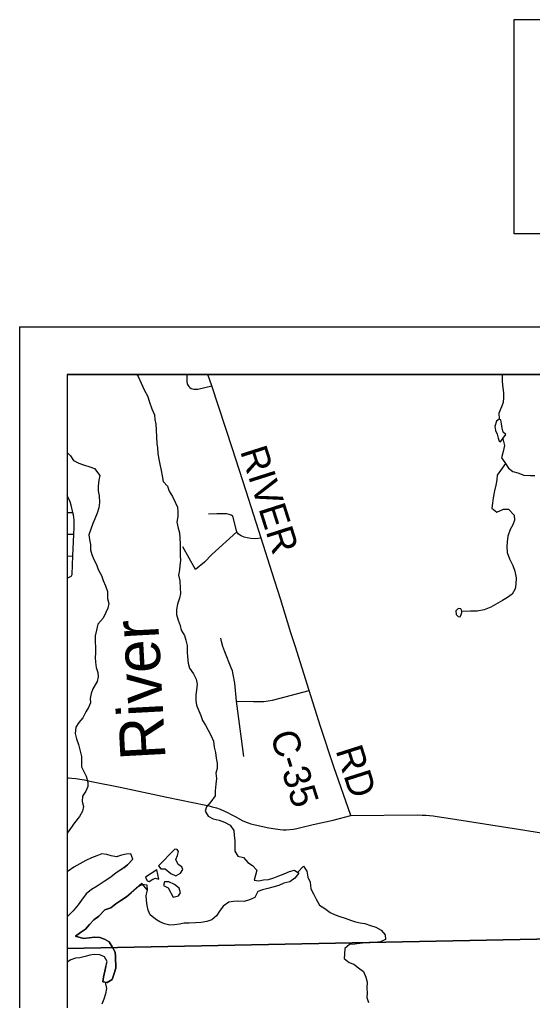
# Model space of a CAD drawing. Extents: x 0 to 34, y 0 to 22.
# Drawn here: x 3.344 to 4.422, y 18.608 to 20.67 of the extents above; entities that cross this region are included whole.
import ezdxf

# ---------------------------------------------------------------- set-up
doc = ezdxf.new("R2010")
doc.units = 0
for name, color, linetype in [('GM_X_Corporation', 7, 'Continuous'), ('GM_X_County_Road', 7, 'Continuous'), ('GM_X_County_Road_Text', 7, 'Continuous'), ('GM_X_Major_Lake', 7, 'Continuous'), ('GM_X_Major_River_Text', 7, 'Continuous'), ('GM_X_Minor_Lake', 7, 'Continuous'), ('GM_X_Minor_River', 7, 'Continuous'), ('GM_X_Township_Road', 7, 'Continuous'), ('SH_Data', 7, 'Continuous'), ('SH_Text', 7, 'Continuous')]:
    doc.layers.add(name, color=color, linetype=linetype)

msp = doc.modelspace()

# ---------------------------------------------------------------- linework, layer by layer
at = {"layer": 'GM_X_Corporation'}
msp.add_lwpolyline([(6.9951, 19.9239), (3.4438, 19.9239), (3.4438, 18.7173), (4.784, 18.7437), (5.4919, 18.7569), (5.8701, 18.7643), (7.0169, 18.7868), (7.0072, 19.2641), (7.0062, 19.3415), (7.0002, 19.6505)], close=True, dxfattribs=at)
msp.add_lwpolyline([(7.0169, 18.7868), (5.8701, 18.7643), (5.4919, 18.7569), (4.784, 18.7437), (3.4438, 18.7173), (3.4438, 13.5923), (3.5133, 13.5939), (4.9278, 13.619), (5.5741, 13.6306), (5.8662, 13.6357), (7.1049, 13.6572)], dxfattribs=at)
at = {"layer": 'GM_X_County_Road'}
for points in [[(4.0404, 18.9967), (4.0048, 19.099), (3.9766, 19.1839), (3.9528, 19.2594), (3.9233, 19.3534), (3.9144, 19.381), (3.9075, 19.4042), (3.8922, 19.4522), (3.8753, 19.5071), (3.8519, 19.5801), (3.8203, 19.6783), (3.7912, 19.7674), (3.748, 19.8997), (3.74, 19.9239)], [(3.4438, 19.0761), (3.4464, 19.076), (3.4536, 19.0756), (3.4619, 19.0746), (3.4703, 19.0735), (3.4804, 19.0716), (3.4953, 19.0685), (3.5551, 19.0562), (3.6537, 19.0356)], [(3.6537, 19.0356), (3.7356, 19.0186), (3.7426, 19.0169), (3.7491, 19.0151), (3.7576, 19.0126), (3.7655, 19.01), (3.7733, 19.0069), (3.7813, 19.0032), (3.7888, 18.9992), (3.7956, 18.9956), (3.7974, 18.9946)], [(3.7974, 18.9946), (3.8135, 18.9859), (3.8224, 18.9819), (3.8299, 18.9796), (3.8365, 18.9776), (3.8457, 18.9756), (3.8683, 18.9709), (3.8821, 18.9685), (3.8916, 18.9671), (3.8982, 18.9667), (3.9045, 18.9668), (3.9119, 18.9671), (3.9198, 18.9681), (3.9267, 18.9693), (3.9328, 18.9709), (3.9613, 18.9778), (4.003, 18.9873), (4.0404, 18.9967)], [(4.0404, 18.9967), (4.1797, 18.9979), (4.1902, 18.9977), (4.1981, 18.9975), (4.2061, 18.9971), (4.2133, 18.9962), (4.2223, 18.9949), (4.25, 18.9904), (4.4062, 18.9661), (4.6004, 18.9348), (4.7799, 18.9077)]]:
    msp.add_lwpolyline(points, dxfattribs=at)
at = {"layer": 'GM_X_Major_Lake'}
for points in [[(3.5906, 19.9239), (3.593, 19.9197), (3.5996, 19.9057), (3.6062, 19.8905), (3.6128, 19.8788), (3.6171, 19.8659), (3.6217, 19.8515), (3.6272, 19.839), (3.628, 19.8295), (3.63, 19.8193), (3.6313, 19.8075), (3.6318, 19.7919), (3.6327, 19.779), (3.6335, 19.7695), (3.6348, 19.7577), (3.6368, 19.7456), (3.6388, 19.735), (3.6415, 19.7221), (3.6439, 19.7107), (3.6459, 19.6989), (3.6548, 19.6891), (3.6583, 19.6785), (3.6652, 19.6671), (3.671, 19.6558), (3.6761, 19.6448), (3.6765, 19.6353), (3.6766, 19.625), (3.6748, 19.6136), (3.6776, 19.6007), (3.68, 19.5909), (3.6808, 19.5802), (3.6817, 19.5669), (3.6814, 19.5555), (3.6812, 19.5434), (3.6824, 19.5331), (3.681, 19.5224), (3.6803, 19.5129), (3.6777, 19.5023), (3.6805, 19.4901), (3.6814, 19.4749), (3.6819, 19.4635), (3.6804, 19.454), (3.6756, 19.4414), (3.6738, 19.4296), (3.6739, 19.419), (3.677, 19.4072), (3.6813, 19.3963), (3.6837, 19.3864), (3.6903, 19.3754), (3.6934, 19.3656), (3.6962, 19.3542), (3.6959, 19.3405), (3.6968, 19.3302), (3.6984, 19.3173), (3.7012, 19.3067), (3.7092, 19.2946), (3.7154, 19.2833), (3.7174, 19.2726), (3.716, 19.2605), (3.7146, 19.2506), (3.7143, 19.2384), (3.7159, 19.2289), (3.721, 19.2168), (3.7249, 19.2069), (3.7284, 19.1967), (3.7349, 19.1869), (3.7404, 19.1759), (3.7469, 19.1646), (3.7516, 19.1532), (3.7528, 19.1407), (3.7556, 19.1293), (3.7572, 19.1175), (3.7592, 19.1065), (3.7593, 19.0955)], [(3.4438, 19.7601), (3.4507, 19.7528), (3.4569, 19.743), (3.4687, 19.7374), (3.4783, 19.7337), (3.4912, 19.73), (3.5015, 19.7263), (3.5123, 19.7115), (3.5105, 19.7016), (3.5091, 19.6894), (3.5092, 19.6796), (3.5112, 19.6686), (3.512, 19.6549), (3.5102, 19.6438), (3.5069, 19.6324), (3.5017, 19.6202), (3.498, 19.6103), (3.4935, 19.5985), (3.4895, 19.5867), (3.4911, 19.5768), (3.4927, 19.5662), (3.4928, 19.5551), (3.4959, 19.5457), (3.5002, 19.5351), (3.5052, 19.5244), (3.5091, 19.5138), (3.5161, 19.501), (3.5196, 19.4907), (3.5246, 19.4798), (3.5289, 19.468), (3.5287, 19.4528), (3.5314, 19.4426), (3.5296, 19.433), (3.5251, 19.4235), (3.5195, 19.4117), (3.5086, 19.3987), (3.5057, 19.3865), (3.5028, 19.3747), (3.5031, 19.3382), (3.5024, 19.3287), (3.5036, 19.3192), (3.5045, 19.3078), (3.508, 19.2976), (3.5092, 19.2881), (3.507, 19.2782), (3.4981, 19.2629), (3.4943, 19.2534), (3.4925, 19.2431), (3.4926, 19.2336), (3.4889, 19.224), (3.4833, 19.2145), (3.4769, 19.2023), (3.4683, 19.1923), (3.4623, 19.1824), (3.4609, 19.1695), (3.4632, 19.1581), (3.4675, 19.146), (3.4707, 19.135), (3.4738, 19.1209), (3.4743, 19.1103), (3.474, 19.0993), (3.4791, 19.0894), (3.4837, 19.0792), (3.4873, 19.0671), (3.4873, 19.0576), (3.4832, 19.048), (3.4761, 19.0373), (3.4755, 19.0263), (3.4782, 19.0161), (3.4764, 19.0062), (3.4697, 18.9947), (3.4595, 18.9817)], [(3.7593, 19.0955), (3.7564, 19.086), (3.7576, 19.0746), (3.7566, 19.0624), (3.7552, 19.0487), (3.7553, 19.0384), (3.7463, 19.0254), (3.7369, 19.0151), (3.7339, 19.0056), (3.7401, 18.9957), (3.7512, 18.9901), (3.7637, 18.9868), (3.7744, 18.9827), (3.7863, 18.9764), (3.7947, 18.965), (3.7952, 18.9551), (3.7964, 18.9441), (3.7967, 18.9217), (3.8028, 18.9115), (3.815, 18.9082), (3.8235, 18.898), (3.8338, 18.892), (3.843, 18.8818), (3.8397, 18.8711), (3.8371, 18.8608), (3.847, 18.8598), (3.8569, 18.8618), (3.8672, 18.8622), (3.8785, 18.8657), (3.8892, 18.87), (3.9005, 18.8743), (3.9115, 18.8789), (3.9218, 18.882), (3.9313, 18.8753), (3.9223, 18.8649), (3.9121, 18.8576), (3.8992, 18.8549), (3.889, 18.8499), (3.8764, 18.8463), (3.8662, 18.8436), (3.8548, 18.8408), (3.8446, 18.8373), (3.8382, 18.8247), (3.8272, 18.8193), (3.8159, 18.8158), (3.8029, 18.8165), (3.7934, 18.8164), (3.7835, 18.8144), (3.7722, 18.806), (3.7639, 18.7956), (3.7579, 18.7857), (3.7481, 18.7773), (3.7379, 18.7741), (3.7254, 18.7718), (3.7136, 18.7709), (3.7006, 18.7704), (3.6896, 18.7703), (3.6801, 18.7687), (3.6695, 18.7667), (3.6596, 18.7663), (3.6485, 18.7692), (3.639, 18.773), (3.6294, 18.779), (3.6187, 18.788), (3.6144, 18.7978), (3.6121, 18.8077), (3.6105, 18.818), (3.61, 18.829), (3.6125, 18.84), (3.6121, 18.8503), (3.6018, 18.8521), (3.5897, 18.8448)], [(3.7593, 19.0955), (3.7564, 19.086), (3.7576, 19.0746), (3.7566, 19.0624), (3.7552, 19.0487), (3.7553, 19.0384), (3.7463, 19.0254), (3.7369, 19.0151), (3.7339, 19.0056), (3.7401, 18.9957), (3.7512, 18.9901), (3.7637, 18.9868), (3.7744, 18.9827), (3.7863, 18.9764), (3.7947, 18.965), (3.7952, 18.9551), (3.7964, 18.9441), (3.7967, 18.9217), (3.8028, 18.9115), (3.815, 18.9082), (3.8235, 18.898), (3.8338, 18.892), (3.843, 18.8818), (3.8397, 18.8711), (3.8371, 18.8608), (3.847, 18.8598), (3.8569, 18.8618), (3.8672, 18.8622), (3.8785, 18.8657), (3.8892, 18.87), (3.9005, 18.8743), (3.9115, 18.8789), (3.9218, 18.882), (3.9313, 18.8753), (3.9223, 18.8649), (3.9121, 18.8576), (3.8992, 18.8549), (3.889, 18.8499), (3.8764, 18.8463), (3.8662, 18.8436), (3.8548, 18.8408), (3.8446, 18.8373), (3.8382, 18.8247), (3.8272, 18.8193), (3.8159, 18.8158), (3.8029, 18.8165), (3.7934, 18.8164), (3.7835, 18.8144), (3.7722, 18.806), (3.7639, 18.7956), (3.7579, 18.7857), (3.7481, 18.7773), (3.7379, 18.7741), (3.7254, 18.7718), (3.7136, 18.7709), (3.7006, 18.7704), (3.6896, 18.7703), (3.6801, 18.7687), (3.6695, 18.7667), (3.6596, 18.7663), (3.6485, 18.7692), (3.639, 18.773), (3.6294, 18.779), (3.6187, 18.788), (3.6144, 18.7978), (3.6121, 18.8077), (3.6105, 18.818), (3.61, 18.829), (3.6125, 18.84), (3.6008, 18.8536)], [(3.4595, 18.9817), (3.4505, 18.9695), (3.4438, 18.9598)], [(3.6359, 18.8909), (3.641, 18.8849), (3.6501, 18.885), (3.662, 18.8752), (3.6723, 18.87), (3.6825, 18.8759), (3.687, 18.8831), (3.685, 18.8892), (3.6773, 18.8937), (3.6726, 18.9043), (3.6756, 18.913), (3.6781, 18.9211), (3.675, 18.9256), (3.6704, 18.9263)], [(3.6704, 18.9263), (3.6359, 18.8909)], [(3.5631, 18.887), (3.5706, 18.8933), (3.5819, 18.9048), (3.5776, 18.9165), (3.5677, 18.9157), (3.5582, 18.9137), (3.5476, 18.9102), (3.5366, 18.9124), (3.527, 18.915), (3.5168, 18.916), (3.5062, 18.9121), (3.4948, 18.9079), (3.483, 18.9024), (3.4702, 18.8951), (3.4577, 18.8882), (3.446, 18.8797), (3.4438, 18.8786)], [(3.5819, 18.9048), (3.5706, 18.8933), (3.56, 18.8844), (3.5468, 18.876), (3.5355, 18.8671), (3.5218, 18.8583), (3.5067, 18.8483), (3.495, 18.841), (3.4837, 18.8325), (3.4739, 18.8188), (3.4668, 18.8092), (3.4566, 18.7962), (3.4453, 18.7851), (3.4438, 18.784)], [(3.5631, 18.887), (3.5468, 18.876), (3.5355, 18.8671), (3.5218, 18.8583), (3.5067, 18.8483), (3.495, 18.841), (3.4837, 18.8325), (3.4739, 18.8188), (3.4668, 18.8092), (3.4566, 18.7962), (3.4453, 18.7851), (3.4438, 18.784)], [(3.6089, 18.8674), (3.612, 18.8598), (3.6166, 18.8583), (3.6241, 18.863), (3.6298, 18.865), (3.6363, 18.8631), (3.6326, 18.8825)], [(3.6326, 18.8825), (3.6089, 18.8674)], [(3.6008, 18.8536), (3.5787, 18.834), (3.5689, 18.8256), (3.5564, 18.8179), (3.5459, 18.811), (3.5357, 18.8025), (3.5231, 18.7982), (3.5107, 18.7852), (3.5001, 18.7775), (3.4911, 18.7676), (3.4821, 18.758), (3.4722, 18.7511), (3.4613, 18.743), (3.4784, 18.7382), (3.4902, 18.7398), (3.5012, 18.7411), (3.5123, 18.7404), (3.5222, 18.7367), (3.5321, 18.731), (3.5383, 18.7208), (3.5449, 18.7099), (3.5457, 18.7004), (3.5459, 18.6757), (3.5422, 18.6623), (3.5382, 18.6524), (3.5283, 18.6455), (3.5188, 18.6473), (3.5199, 18.6572), (3.5228, 18.6694), (3.5254, 18.6793)], [(3.5254, 18.6793), (3.5228, 18.6694), (3.5199, 18.6572), (3.5188, 18.6473), (3.5283, 18.6455), (3.5382, 18.6524), (3.5422, 18.6623), (3.5459, 18.6757), (3.5457, 18.7004), (3.5449, 18.7099), (3.5383, 18.7208), (3.5321, 18.731), (3.5222, 18.7367), (3.5123, 18.7404), (3.5012, 18.7411), (3.4902, 18.7398), (3.4784, 18.7382), (3.4613, 18.743), (3.4722, 18.7511), (3.4821, 18.758), (3.4911, 18.7676), (3.5001, 18.7775), (3.5107, 18.7852), (3.5231, 18.7982), (3.5357, 18.8025), (3.5459, 18.811), (3.5564, 18.8179), (3.5689, 18.8256), (3.5787, 18.834), (3.5897, 18.8448)], [(3.6665, 18.8255), (3.6779, 18.8283), (3.682, 18.8344), (3.6795, 18.8439), (3.6699, 18.8521), (3.6577, 18.8577), (3.6482, 18.8576), (3.6464, 18.8499), (3.6563, 18.8451)], [(3.6563, 18.8451), (3.6665, 18.8255)], [(3.5254, 18.6793), (3.5279, 18.6896), (3.5225, 18.6998), (3.5122, 18.7043), (3.5008, 18.7046), (3.4913, 18.703), (3.4814, 18.7002), (3.4708, 18.6979), (3.4613, 18.6966), (3.4518, 18.6931), (3.4438, 18.6886)]]:
    msp.add_lwpolyline(points, dxfattribs=at)
at = {"layer": 'GM_X_Minor_Lake'}
for points in [[(4.3667, 19.7977), (4.3605, 19.8029), (4.3587, 19.8112), (4.3574, 19.8203), (4.3561, 19.8282), (4.3526, 19.8301), (4.347, 19.8257), (4.3434, 19.8146), (4.3448, 19.8059), (4.348, 19.7984), (4.3501, 19.7897), (4.3522, 19.7837), (4.3552, 19.7822)], [(4.3552, 19.7822), (4.3667, 19.7977)], [(4.2714, 19.4313), (4.2672, 19.4319), (4.2646, 19.4307), (4.2609, 19.4272), (4.2618, 19.4193), (4.2661, 19.4152), (4.2703, 19.4145), (4.2721, 19.4191)], [(4.2721, 19.4191), (4.2737, 19.4236), (4.2741, 19.4259), (4.2735, 19.4283), (4.2714, 19.4313)]]:
    msp.add_lwpolyline(points, dxfattribs=at)
at = {"layer": 'GM_X_Minor_River'}
for points in [[(4.3588, 19.9239), (4.3585, 19.9203), (4.3587, 19.9093), (4.3598, 19.896), (4.3612, 19.8854), (4.3614, 19.8755), (4.3605, 19.8652), (4.3573, 19.8556), (4.3519, 19.8422), (4.3524, 19.8299)], [(4.3602, 19.7889), (4.3638, 19.7748), (4.361, 19.7618), (4.3572, 19.7488), (4.3642, 19.7391), (4.3717, 19.7271), (4.3814, 19.7201), (4.3918, 19.7169), (4.4044, 19.7119), (4.4177, 19.7118), (4.4276, 19.7117)], [(4.3658, 19.7366), (4.3485, 19.7121), (4.3476, 19.7026), (4.3452, 19.6915), (4.3428, 19.6793), (4.3394, 19.6648), (4.3381, 19.6533), (4.3372, 19.6427), (4.3473, 19.6345), (4.3616, 19.6409), (4.3723, 19.6404), (4.384, 19.6278), (4.3849, 19.6179), (4.381, 19.6079), (4.3755, 19.5979), (4.3709, 19.5838), (4.3689, 19.5719), (4.3684, 19.5616), (4.3694, 19.5495), (4.3743, 19.5363), (4.3811, 19.5224), (4.3852, 19.5103), (4.3882, 19.4963), (4.3877, 19.483), (4.3861, 19.4735), (4.3795, 19.4623), (4.3697, 19.4552), (4.3592, 19.4489), (4.345, 19.4406), (4.3345, 19.4346), (4.3205, 19.429), (4.3058, 19.426), (4.2921, 19.426), (4.2741, 19.4259)], [(3.9285, 18.8773), (3.9411, 18.8906), (3.9476, 18.8796), (3.9497, 18.8674), (3.9547, 18.8565), (3.9563, 18.8428), (3.9618, 18.8322), (3.9676, 18.8212), (3.9745, 18.8084), (3.9856, 18.8016), (3.9971, 18.793), (4.0074, 18.7881), (4.0173, 18.7848), (4.0284, 18.7807), (4.0395, 18.777), (4.0505, 18.7736), (4.0601, 18.771), (4.07, 18.7696), (4.0818, 18.7659), (4.0929, 18.7622), (4.1043, 18.7558), (4.1128, 18.746), (4.1132, 18.7365), (4.1026, 18.7311), (4.0912, 18.7302), (4.081, 18.7294), (4.0711, 18.7289), (4.0593, 18.7277), (4.0487, 18.7265), (4.0377, 18.7256), (4.0278, 18.7172), (4.0268, 18.7054), (4.0265, 18.6959), (4.0368, 18.688), (4.0464, 18.6846), (4.0567, 18.6767), (4.0667, 18.6688), (4.0717, 18.6567), (4.0745, 18.6465), (4.0742, 18.6347), (4.0747, 18.6237), (4.0744, 18.6142), (4.0775, 18.6036)], [(3.5237, 18.6464), (3.5265, 18.6329), (3.5244, 18.6219), (3.521, 18.6108), (3.5169, 18.6006)]]:
    msp.add_lwpolyline(points, dxfattribs=at)
at = {"layer": 'GM_X_Township_Road'}
for p, q in [((3.4438, 19.6336), (3.456, 19.6338)), ((3.4578, 19.5874), (3.4438, 19.5874)), ((3.714, 19.5137), (3.6868, 19.5616)), ((3.4438, 19.5422), (3.4555, 19.5425))]:
    msp.add_line(p, q, dxfattribs=at)
for points in [[(3.6952, 19.9239), (3.6957, 19.9087), (3.6964, 19.9052), (3.6969, 19.903), (3.6983, 19.9007), (3.6998, 19.8987), (3.7016, 19.8965), (3.7045, 19.8945), (3.7074, 19.8934), (3.7103, 19.8929), (3.7136, 19.8928), (3.7183, 19.8932), (3.748, 19.8997)], [(3.452, 19.4998), (3.4529, 19.5006), (3.4537, 19.5017), (3.4541, 19.5034), (3.4555, 19.5425), (3.4578, 19.5874), (3.4586, 19.6032), (3.4587, 19.6082), (3.4587, 19.6129), (3.4585, 19.6179), (3.458, 19.6234), (3.4571, 19.629), (3.456, 19.6338), (3.4522, 19.649), (3.4498, 19.6564), (3.4463, 19.6641), (3.4438, 19.6688)], [(3.8005, 19.5932), (3.792, 19.6262), (3.789, 19.6283), (3.7848, 19.6296), (3.7786, 19.6307), (3.7584, 19.6312), (3.7411, 19.6302)], [(3.8519, 19.5801), (3.8398, 19.5787), (3.83, 19.5794), (3.8223, 19.5803), (3.8161, 19.5817), (3.8099, 19.5848), (3.8043, 19.5885), (3.8005, 19.5932), (3.7482, 19.5455), (3.7324, 19.5295), (3.714, 19.5137)], [(3.4438, 19.497), (3.4465, 19.4973), (3.4495, 19.4983), (3.452, 19.4998)], [(3.8152, 19.1212), (3.8003, 19.2374), (3.7967, 19.2748), (3.7929, 19.2935), (3.7912, 19.3006), (3.7884, 19.3071), (3.7756, 19.341), (3.7711, 19.3524), (3.7683, 19.3625), (3.7668, 19.3697)], [(3.8003, 19.2374), (3.8359, 19.2362), (3.8464, 19.2362), (3.8576, 19.2366), (3.8664, 19.2376), (3.876, 19.2391), (3.9528, 19.2594)]]:
    msp.add_lwpolyline(points, dxfattribs=at)
at = {"layer": 'SH_Data'}
for p, q in [((3.3438, 20.0239), (10.3438, 20.0239)), ((3.3438, 20.0239), (3.3438, 13.0239)), ((3.4438, 19.9239), (3.4438, 13.1239)), ((3.4438, 19.9239), (10.2438, 19.9239))]:
    msp.add_line(p, q, dxfattribs=at)
at = {"layer": 'SH_Text'}
msp.add_lwpolyline([(4.3838, 20.6698), (6.2084, 20.6698), (6.2084, 20.2198), (4.3838, 20.2198)], close=True, dxfattribs=at)

# ---------------------------------------------------------------- texts
at = {"layer": 'GM_X_County_Road_Text'}
for s, rotation, p in [('RIVER', 287.6688, (3.8072, 19.763)), ('C-35', 287.7834, (3.8702, 19.166)), ('RD', 287.65, (4.008, 19.1338))]:
    msp.add_text(s, height=0.05682, rotation=rotation, dxfattribs=at).set_placement(p)
at = {"layer": 'GM_X_Major_River_Text'}
msp.add_text('River', height=0.09473, rotation=93.0788, dxfattribs=at).set_placement((3.6509, 19.1159))

doc.saveas('drawing.dxf')
